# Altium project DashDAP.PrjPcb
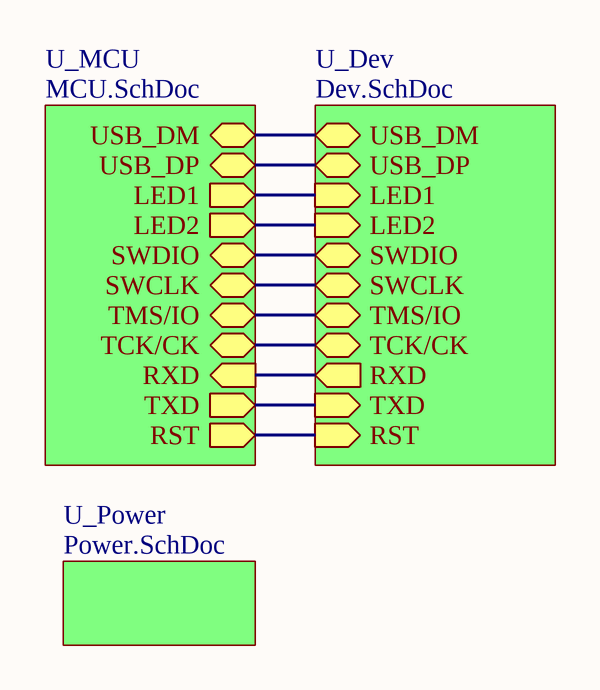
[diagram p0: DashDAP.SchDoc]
4 sheets, 30 parts. Net scope: hierarchical (ports join the sheet entries above them; power ports are global).
Board file: DashDAP.PcbDoc
Sheets:
  DashDAP.SchDoc
    U_MCU = MCU.SchDoc
    U_Power = Power.SchDoc
    U_Dev = Dev.SchDoc

## Sheet DashDAP.SchDoc
size 292 x 193 mm; Author: Power Lin; DocumentNumber: 1; SheetNumber: 1; SheetTotal: 4; Website: wiki-power.com

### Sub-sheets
U_Dev = Dev.SchDoc: USB_DM (bidir), USB_DP (bidir), LED1 (in), LED2 (in), SWDIO (bidir), SWCLK (bidir), TMS/IO (bidir), TCK/CK (bidir), TXD (in), RXD (out), RST (in)
U_MCU = MCU.SchDoc: LED1 (out), LED2 (out), TMS/IO (bidir), TCK/CK (bidir), RST (out), TXD (out), RXD (in), USB_DM (bidir), USB_DP (bidir), SWDIO (bidir), SWCLK (bidir)
U_Power = Power.SchDoc: no entries

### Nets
USB_N: sheet U_MCU/USB_DM, sheet U_Dev/USB_DM
USB_P: sheet U_MCU/USB_DP, sheet U_Dev/USB_DP
NetP1_1: sheet U_MCU/SWCLK, sheet U_Dev/SWCLK
NetP1_2: sheet U_MCU/SWDIO, sheet U_Dev/SWDIO
NetP3_2: sheet U_MCU/RST, sheet U_Dev/RST
NetP3_3: sheet U_MCU/RXD, sheet U_Dev/RXD
NetP3_4: sheet U_MCU/TXD, sheet U_Dev/TXD
NetR4_1: sheet U_MCU/TCK/CK, sheet U_Dev/TCK/CK
NetR6_2: sheet U_MCU/LED1, sheet U_Dev/LED1
NetR7_2: sheet U_MCU/LED2, sheet U_Dev/LED2
NetR9_1: sheet U_MCU/TMS/IO, sheet U_Dev/TMS/IO

## Sheet MCU.SchDoc
size 292 x 193 mm; Author: Power Lin; DocumentNumber: 2; SheetNumber: 2; SheetTotal: 4; Website: wiki-power.com
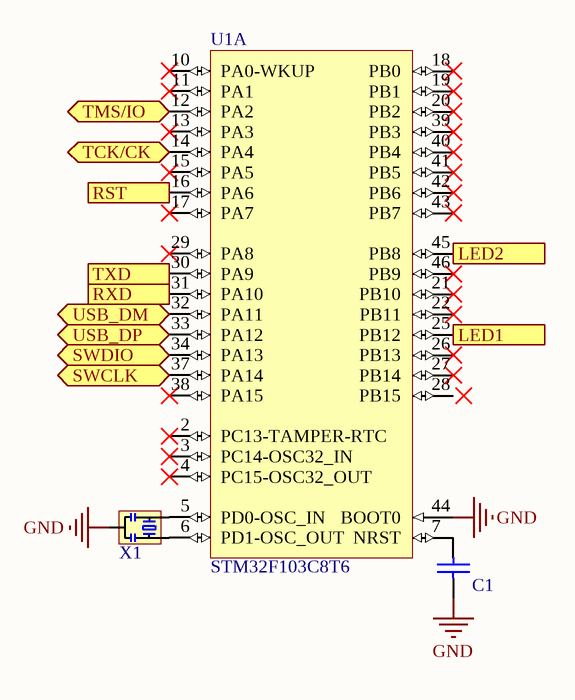
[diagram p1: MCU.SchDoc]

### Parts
C1  100nF  [CAP-0603]  (value not drawn)
U1  STM32F103C8T6  [LQFP_48]  (part A of 2)
X1  8MHz  [CSTCE_G(A)村田晶振]  (value not drawn)

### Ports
LED1 (out), LED2 (out), RST (out), RXD (in), SWCLK (bidir), SWDIO (bidir), TCK/CK (bidir), TMS/IO (bidir), TXD (out), USB_DM (bidir), USB_DP (bidir)

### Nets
GND: C1.2 U1.44(BOOT0) X1.2(GND)
USB_N: U1.32(PA11) ; port USB_DM
USB_P: U1.33(PA12) ; port USB_DP
NetC1_1: C1.1 U1.7(NRST)
NetP1_1: U1.37(PA14) ; port SWCLK
NetP1_2: U1.34(PA13) ; port SWDIO
NetP3_2: U1.16(PA6) ; port RST
NetP3_3: U1.31(PA10) ; port RXD
NetP3_4: U1.30(PA9) ; port TXD
NetR4_1: U1.14(PA4) ; port TCK/CK
NetR6_2: U1.25(PB12) ; port LED1
NetR7_2: U1.45(PB8) ; port LED2
NetR9_1: U1.12(PA2) ; port TMS/IO
NetU1_5: U1.5(PD0-OSC_IN) X1.1(OSC1)
NetU1_6: U1.6(PD1-OSC_OUT) X1.3(OSC2)

Not connected (* = marked no-connect by the designer): U1 2(PC13-TAMPER-RTC)* 3(PC14-OSC32_IN)* 4(PC15-OSC32_OUT)* 10(PA0-WKUP)* 11(PA1)* 13(PA3)* 15(PA5)* 17(PA7)* 18(PB0)* 19(PB1)* 20(PB2)* 21(PB10)* 22(PB11)* 26(PB13)* 27(PB14)* 28(PB15) 29(PA8)* 38(PA15)* 39(PB3)* 40(PB4)* 41(PB5)* 42(PB6)* 43(PB7)* 46(PB9)*

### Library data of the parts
C1 = CAP: 贴片电容
U1 = STM32F103Cx: 单片机; PartNumber: STM32F100C8T6B; A/D Converter: 1x12-bit (10 Channel); Core: ARM Cortex-M3; D/A Converter: 2x12-bit (2 Channel); FLASH Size (Prog) (kB): 64; I/Os (High Current): 37; Internal RAM Size (kB): 8; Operating Frequency(F) (Processor speed) (MHz): 24; Packing: Tray; Supply Voltage(Vcc) min (V): 2
X1 = XTAL: 有源晶振

## Sheet Power.SchDoc
size 292 x 193 mm; Author: Power Lin; DocumentNumber: 4; SheetNumber: 4; SheetTotal: 4; Website: wiki-power.com
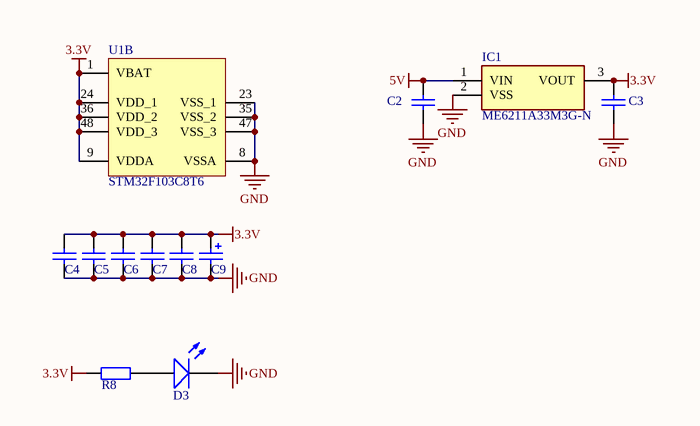
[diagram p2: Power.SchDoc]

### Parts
C2  1uF  [CAP-0603]  (value not drawn)
C3  1uF  [CAP-0603]  (value not drawn)
C4  100nF  [CAP-0603]  (value not drawn)
C5  100nF  [CAP-0603]  (value not drawn)
C6  100nF  [CAP-0603]  (value not drawn)
C7  100nF  [CAP-0603]  (value not drawn)
C8  100nF  [CAP-0603]  (value not drawn)
C9  10uF  [CASE-B_3528]  (value not drawn)
D3  RED  [LED-0603]  (value not drawn)
IC1  ME6211A33M3G-N  [SOT-23-3]
R8  10K  [R-0603]  (value not drawn)
U1  STM32F103C8T6  [LQFP_48]  (part B of 2)

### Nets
3.3V: C3.2 C4.2 C5.2 C6.2 C7.2 C8.2 C9.1 IC1.3(VOUT) R8.2 U1.1(VBAT) U1.9(VDDA) U1.24(VDD_1) U1.36(VDD_2) U1.48(VDD_3)
5V: C2.2 IC1.1(VIN)
GND: C2.1 C3.1 C4.1 C5.1 C6.1 C7.1 C8.1 C9.2 D3.K IC1.2(VSS) U1.8(VSSA) U1.23(VSS_1) U1.35(VSS_2) U1.47(VSS_3)
NetD3_A: D3.A R8.1

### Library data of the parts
C2-C8 = CAP: 贴片电容
C9 = CAP-POL: 贴片电容-有极性
D3 = LED: 发光二极管; pin to pad: A>1 K>2
IC1 = ME6211A33M3G-N: 线性稳压; Manufacturer_Name: Nexperia; Manufacturer_Part_Number: SI2302DS
R8 = RES: 贴片电阻
U1 = STM32F103Cx: as U1 on sheet MCU

## Sheet Dev.SchDoc
size 292 x 193 mm; Author: Power Lin; DocumentNumber: 3; SheetNumber: 3; SheetTotal: 4; Website: wiki-power.com
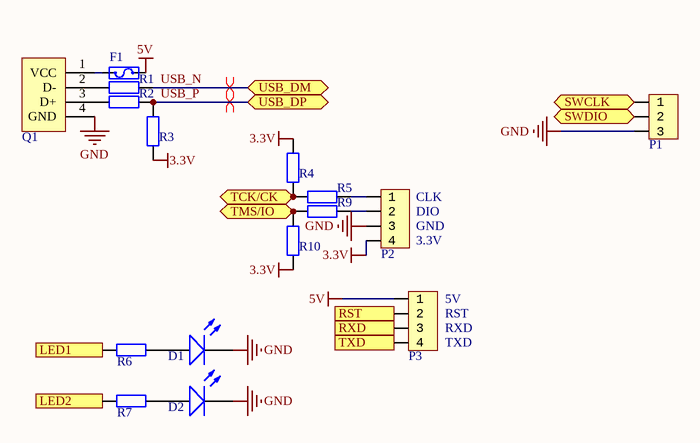
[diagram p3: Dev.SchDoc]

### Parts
D1  RED  [LED-0603]  (value not drawn)
D2  GREEN  [LED-0603]  (value not drawn)
F1  Fuse  [R-0603]  (value not drawn)
P1  HDR1x3_2.54  [HDR1X3_2.54_180]  (value not drawn)
P2  HDR1x4_2.54  [HDR1X4_2.54_180H]  (value not drawn)
P3  HDR1x4_2.54  [HDR1X4_2.54_180H]  (value not drawn)
Q1  USB A  [USB_A(M)_DIP]  (value not drawn)
R1  22R  [R-0603]  (value not drawn)
R2  22R  [R-0603]  (value not drawn)
R3  1.5K  [R-0603]  (value not drawn)
R4  1R  [R-0603]  (value not drawn)
R5  22R  [R-0603]  (value not drawn)
R6  10K  [R-0603]  (value not drawn)
R7  10K  [R-0603]  (value not drawn)
R9  22R  [R-0603]  (value not drawn)
R10  1R  [R-0603]  (value not drawn)

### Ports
LED1 (in), LED2 (in), RST (in), RXD (out), SWCLK (bidir), SWDIO (bidir), TCK/CK (bidir), TMS/IO (bidir), TXD (in), USB_DM (bidir), USB_DP (bidir)

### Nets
3.3V: P2.4 R3.1 R4.2 R10.1
5V: F1.2 P3.1
GND: D1.K D2.K P1.3 P2.3 Q1.4(GND)
USB_N: R1.2 ; port USB_DM
USB_P: R2.2 R3.2 ; port USB_DP
NetD1_A: D1.A R6.1
NetD2_A: D2.A R7.1
NetF1_1: F1.1 Q1.1(VCC)
NetP1_1: P1.1 ; port SWCLK
NetP1_2: P1.2 ; port SWDIO
NetP2_1: P2.1 R5.2
NetP2_2: P2.2 R9.2
NetP3_2: P3.2 ; port RST
NetP3_3: P3.3 ; port RXD
NetP3_4: P3.4 ; port TXD
NetQ1_2: Q1.2(D-) R1.1
NetQ1_3: Q1.3(D+) R2.1
NetR4_1: R4.1 R5.1 ; port TCK/CK
NetR6_2: R6.2 ; port LED1
NetR7_2: R7.2 ; port LED2
NetR9_1: R9.1 R10.2 ; port TMS/IO

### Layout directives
differential pair: USB_N, USB_P

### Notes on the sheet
- (near P2) CLK
- (near P2) DIO
- (near P2) GND
- 3.3V
- (near P3) RXD
- (near P3) RST
- (near P3) 5V
- (near P3) TXD

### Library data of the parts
D1 D2 = LED: 发光二极管; pin to pad: A>1 K>2
F1 = Fuse: 6V 500mA 保险丝
P1 = HDR1x3_2.54: Header
P2 P3 = HDR1x4_2.54: Header
Q1 = USB A: USB 接口
R1-R7 R9 R10 = RES: 贴片电阻

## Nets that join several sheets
3.3V: Power (14 pins), Dev (P2.4 R3.1 R4.2 R10.1)
5V: Power (C2.2 IC1.1), Dev (F1.2 P3.1)
GND: MCU (C1.2 U1.44 X1.2), Power (14 pins), Dev (5 pins)
NetP1_1: MCU (U1.37), Dev (P1.1)
NetP1_2: MCU (U1.34), Dev (P1.2)
NetP3_2: MCU (U1.16), Dev (P3.2)
NetP3_3: MCU (U1.31), Dev (P3.3)
NetP3_4: MCU (U1.30), Dev (P3.4)
NetR4_1: MCU (U1.14), Dev (R4.1 R5.1)
NetR6_2: MCU (U1.25), Dev (R6.2)
NetR7_2: MCU (U1.45), Dev (R7.2)
NetR9_1: MCU (U1.12), Dev (R9.1 R10.2)
USB_N: MCU (U1.32), Dev (R1.2)
USB_P: MCU (U1.33), Dev (R2.2 R3.2)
